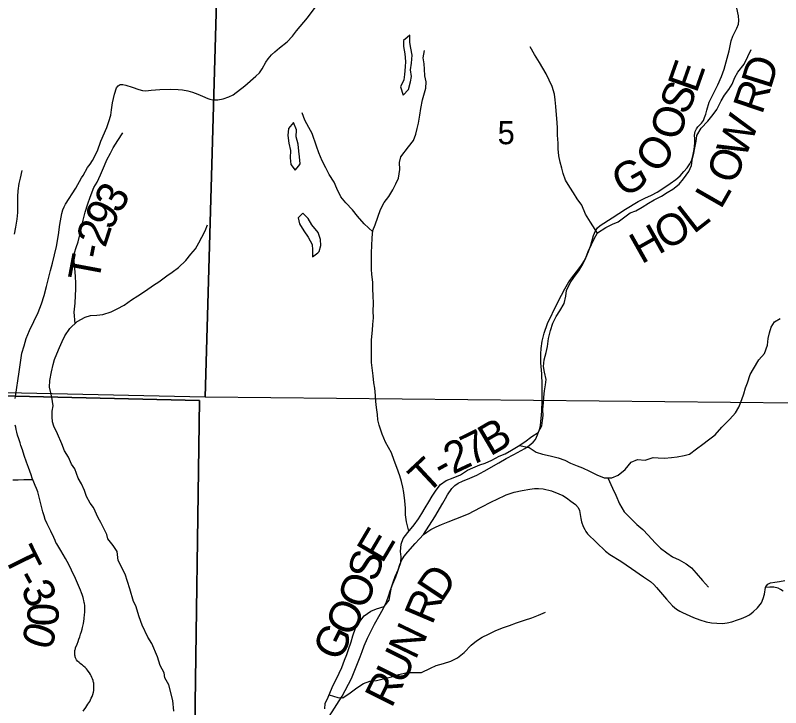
# Model space of a CAD drawing. Extents: x 0 to 34, y 0 to 22.
# Drawn here: x 5.34 to 6.729, y 17.07 to 18.326 of the extents above; entities that cross this region are included whole.
import ezdxf

# ---------------------------------------------------------------- set-up
doc = ezdxf.new("R2010")
doc.units = 0
for name, color, linetype in [('GM_X_County_Road', 7, 'Continuous'), ('GM_X_County_Road_Text', 7, 'Continuous'), ('GM_X_Minor_Lake', 7, 'Continuous'), ('GM_X_Minor_River', 7, 'Continuous'), ('GM_X_Rail_Line', 7, 'Continuous'), ('GM_X_Section', 7, 'Continuous'), ('GM_X_Section_Text', 7, 'Continuous'), ('GM_X_Township_Road', 7, 'Continuous'), ('GM_X_Township_Road_Text', 7, 'Continuous'), ('SH_Cut_Line', 7, 'Continuous')]:
    doc.layers.add(name, color=color, linetype=linetype)

msp = doc.modelspace()

# ---------------------------------------------------------------- linework, layer by layer
at = {"layer": 'GM_X_County_Road'}
for points in [[(6.081, 17.3843), (6.0871, 17.3887), (6.0943, 17.3932), (6.1037, 17.3984), (6.1137, 17.4027), (6.1257, 17.4074), (6.1397, 17.4129), (6.1623, 17.4221), (6.1845, 17.4331), (6.2053, 17.4442), (6.2131, 17.4481), (6.231, 17.4564), (6.2379, 17.4589), (6.2455, 17.461), (6.26, 17.4643), (6.2738, 17.4668), (6.2822, 17.4676), (6.2892, 17.4677), (6.2977, 17.467), (6.3129, 17.4634), (6.3261, 17.4583), (6.3335, 17.455), (6.3402, 17.451), (6.3484, 17.4448), (6.3565, 17.4387), (6.3614, 17.4336), (6.3641, 17.4282), (6.3661, 17.4136), (6.3677, 17.4073), (6.3706, 17.3991), (6.3734, 17.3936), (6.3756, 17.3901), (6.3785, 17.3858), (6.411, 17.3543), (6.4186, 17.3482), (6.439, 17.336), (6.4582, 17.323), (6.4802, 17.3076), (6.4927, 17.2993), (6.4984, 17.294), (6.5035, 17.2884), (6.5219, 17.267), (6.5325, 17.2553), (6.5397, 17.2491), (6.5458, 17.2452), (6.5504, 17.243), (6.5572, 17.2399), (6.5708, 17.2337), (6.5819, 17.2299), (6.5934, 17.2262), (6.6034, 17.2243), (6.6132, 17.2234), (6.623, 17.2233), (6.6316, 17.2241), (6.6405, 17.2263), (6.6505, 17.2299), (6.6577, 17.2321), (6.6665, 17.2356), (6.6724, 17.239), (6.679, 17.2441), (6.6868, 17.2516), (6.694, 17.2605), (6.6972, 17.2682), (6.6992, 17.2763), (6.7012, 17.2882), (6.7029, 17.2912), (6.7055, 17.2944), (6.7102, 17.297), (6.718, 17.2979), (6.7266, 17.2991), (6.7365, 17.3011)], [(5.9098, 17.0546), (5.9333, 17.0913), (5.9505, 17.1232), (5.9661, 17.1623), (5.9694, 17.1724), (5.9731, 17.1826), (5.9794, 17.1961), (5.9917, 17.2215), (6.0022, 17.2398), (6.0083, 17.2507), (6.014, 17.2625), (6.0173, 17.2725), (6.0202, 17.2822), (6.025, 17.2951), (6.0305, 17.3075), (6.0338, 17.3164), (6.0379, 17.3301), (6.0412, 17.3372), (6.0458, 17.345), (6.0527, 17.3529), (6.0657, 17.3679), (6.0733, 17.3767), (6.081, 17.3843)]]:
    msp.add_lwpolyline(points, dxfattribs=at)
at = {"layer": 'GM_X_Minor_Lake'}
for points in [[(6.044, 18.1813), (6.0534, 18.1916), (6.0575, 18.2053), (6.059, 18.2148), (6.0574, 18.2269), (6.0593, 18.2394), (6.06, 18.2535), (6.0576, 18.2663), (6.0561, 18.2766), (6.056, 18.2899), (6.0513, 18.286)], [(6.0513, 18.286), (6.0443, 18.2803), (6.0447, 18.2693), (6.047, 18.2564), (6.0479, 18.242), (6.0475, 18.2325), (6.0465, 18.2189), (6.045, 18.209), (6.0393, 18.1965), (6.044, 18.1813)], [(5.8452, 18.1319), (5.8361, 18.1208), (5.8347, 18.1079), (5.8366, 18.0939), (5.8393, 18.0807), (5.839, 18.0678), (5.8402, 18.0552), (5.8479, 18.045), (5.8544, 18.0529)], [(5.8544, 18.0529), (5.8573, 18.0565), (5.8561, 18.0693), (5.8545, 18.0796), (5.8533, 18.0925), (5.8499, 18.1057), (5.8502, 18.1183), (5.8452, 18.1319)], [(5.8619, 17.967), (5.8536, 17.959), (5.8559, 17.948), (5.8635, 17.9351), (5.8719, 17.9234), (5.8788, 17.9101), (5.8796, 17.9007), (5.8793, 17.8878), (5.8889, 17.8954)], [(5.8889, 17.8954), (5.8918, 17.8977), (5.8944, 17.9087), (5.894, 17.9197), (5.8897, 17.9322), (5.8783, 17.9458), (5.8718, 17.9575), (5.8619, 17.967)]]:
    msp.add_lwpolyline(points, dxfattribs=at)
at = {"layer": 'GM_X_Minor_River'}
for points in [[(6.0543, 17.3905), (6.05, 17.4073), (6.0484, 17.4198), (6.048, 17.4319), (6.0471, 17.4455), (6.0451, 17.4603), (6.0432, 17.4702), (6.0412, 17.4804), (6.0381, 17.4906), (6.0323, 17.5058), (6.0277, 17.5186), (6.0226, 17.5326), (6.0122, 17.5519), (6.0057, 17.5663), (6.0003, 17.5829), (5.9983, 17.5924), (5.9971, 17.6022), (5.9955, 17.6148), (5.9943, 17.6257), (5.9935, 17.6367), (5.9926, 17.65), (5.991, 17.6595), (5.9898, 17.672), (5.9882, 17.6818), (5.9866, 17.6966), (5.9863, 17.7376), (5.9881, 17.7547), (5.9892, 17.7653), (5.9899, 17.7771), (5.9898, 17.7899), (5.9901, 17.8025), (5.9896, 17.8184), (5.9892, 17.829), (5.9887, 17.8419), (5.9871, 17.8559), (5.9863, 17.8654), (5.9866, 17.8787), (5.9864, 17.8961), (5.9871, 17.9079), (5.9878, 17.9227), (5.9892, 17.9356), (5.9933, 17.9462), (5.9978, 17.9599), (6.003, 17.9736), (6.0094, 17.9866), (6.0177, 17.9972), (6.0252, 18.0098), (6.0308, 18.0205), (6.0353, 18.0307), (6.0382, 18.0463), (6.0374, 18.0592), (6.0396, 18.0694), (6.0539, 18.0877), (6.0626, 18.0992), (6.067, 18.1106), (6.0696, 18.1205), (6.0719, 18.1303), (6.074, 18.1451), (6.0758, 18.1573), (6.0792, 18.1725), (6.0851, 18.1938), (6.0854, 18.2051), (6.0834, 18.2161), (6.0826, 18.2283), (6.0822, 18.2381), (6.0802, 18.2487), (6.0824, 18.2624)], [(6.3962, 17.9312), (6.3836, 17.9511), (6.3748, 17.9654), (6.3682, 17.9817), (6.3598, 17.993), (6.3529, 18.004), (6.3464, 18.0142), (6.3387, 18.027), (6.3344, 18.0391), (6.3317, 18.049), (6.3286, 18.0599), (6.3266, 18.0713), (6.3254, 18.0838), (6.3253, 18.0944), (6.3241, 18.1085), (6.324, 18.1214), (6.3236, 18.1316), (6.322, 18.1456), (6.3211, 18.1604), (6.3199, 18.1729), (6.3183, 18.1828), (6.314, 18.1968), (6.309, 18.2085), (6.3033, 18.2198), (6.291, 18.2402), (6.2825, 18.255), (6.2741, 18.2686)], [(6.336, 17.8032), (6.3389, 17.8169), (6.3404, 17.8271), (6.3471, 17.8408), (6.3535, 17.8507), (6.3629, 17.8629), (6.3697, 17.8747), (6.3757, 17.888), (6.3798, 17.8976), (6.3858, 17.9101), (6.3907, 17.9208), (6.3963, 17.9314), (6.4118, 17.941), (6.4239, 17.9472), (6.4337, 17.9514), (6.4439, 17.9587), (6.456, 17.9678), (6.4659, 17.9717), (6.4776, 17.9782), (6.489, 17.9851), (6.4992, 17.9913), (6.5128, 17.9982), (6.5226, 18.0047), (6.5332, 18.0108), (6.5445, 18.0196), (6.5528, 18.0292), (6.5619, 18.0425), (6.5671, 18.0539), (6.5689, 18.0668), (6.5711, 18.0763), (6.573, 18.0858), (6.5752, 18.0976), (6.577, 18.1082), (6.5845, 18.1215), (6.5969, 18.1338), (6.6064, 18.146), (6.6131, 18.1555), (6.621, 18.1711), (6.627, 18.1814), (6.6345, 18.1913), (6.6409, 18.2012), (6.6458, 18.2133), (6.651, 18.2229), (6.6623, 18.2377), (6.6695, 18.2514), (6.6754, 18.264)], [(5.989, 17.9332), (5.9732, 17.948), (5.9613, 17.9616), (5.9521, 17.9733), (5.9399, 17.9861), (5.9311, 17.997), (5.9238, 18.0118), (5.9188, 18.0235), (5.91, 18.0375), (5.9034, 18.0492), (5.8969, 18.0624), (5.8911, 18.0764), (5.8865, 18.0889), (5.8787, 18.1116), (5.8726, 18.1226), (5.8653, 18.1358), (5.8606, 18.1491)], [(5.4487, 17.7668), (5.4469, 17.7879), (5.449, 17.8042), (5.4497, 17.8179), (5.45, 17.8293), (5.4499, 17.8403), (5.4495, 17.8524), (5.4482, 17.8676), (5.447, 17.8801), (5.4477, 17.8953), (5.451, 17.9048), (5.4544, 17.9154), (5.4566, 17.9253), (5.4592, 17.9348), (5.461, 17.9443), (5.4636, 17.9545), (5.4673, 17.969), (5.4718, 17.9842), (5.4762, 17.9963), (5.483, 18.0135), (5.4886, 18.0234), (5.4946, 18.0367), (5.5021, 18.0534), (5.5062, 18.0641), (5.5129, 18.0762), (5.5178, 18.0857), (5.5261, 18.0991), (5.5351, 18.1128)], [(5.3388, 17.9294), (5.3414, 17.9416), (5.344, 17.9564), (5.3447, 17.9686), (5.345, 17.9815), (5.3452, 17.9974), (5.3455, 18.0076), (5.3474, 18.0209), (5.3496, 18.0304), (5.3529, 18.0445)], [(5.4068, 17.6332), (5.4026, 17.6518), (5.4032, 17.6636), (5.4062, 17.6792), (5.4088, 17.6925), (5.4117, 17.702), (5.4158, 17.7122), (5.4203, 17.7233), (5.4252, 17.7347), (5.43, 17.7449), (5.4395, 17.7579), (5.4527, 17.7705), (5.467, 17.7786), (5.4769, 17.7813), (5.4883, 17.7825), (5.4989, 17.7837), (5.5141, 17.788), (5.5254, 17.7934), (5.5379, 17.8003), (5.5511, 17.8098), (5.5625, 17.8171), (5.5768, 17.8263), (5.5912, 17.8367), (5.601, 17.8428), (5.615, 17.8535), (5.6248, 17.8604), (5.6362, 17.8688), (5.6494, 17.8814), (5.6588, 17.8929), (5.6671, 17.9024), (5.6731, 17.9134), (5.6787, 17.9237), (5.6847, 17.9351), (5.6892, 17.9462)], [(5.9019, 17.068), (5.9026, 17.0782), (5.9078, 17.0896), (5.9123, 17.0999), (5.9172, 17.1113), (5.9224, 17.1212), (5.9281, 17.133), (5.9329, 17.1433), (5.9378, 17.1562), (5.9415, 17.1665), (5.9449, 17.176), (5.9497, 17.1897), (5.9527, 17.2007), (5.9575, 17.2144), (5.9654, 17.2265), (5.9733, 17.2372), (5.985, 17.2456), (5.9956, 17.2499), (6.0097, 17.2538), (6.0187, 17.2652), (6.0201, 17.2754), (6.0227, 17.2887), (6.0257, 17.2982), (6.0294, 17.3081), (6.0354, 17.3214), (6.0395, 17.3336), (6.0406, 17.3439), (6.039, 17.3533), (6.0404, 17.367), (6.0438, 17.3769), (6.0524, 17.3883), (6.0637, 17.402), (6.072, 17.4127), (6.078, 17.4226), (6.0837, 17.4329), (6.0908, 17.4436), (6.0964, 17.4538), (6.104, 17.4649), (6.1119, 17.4748), (6.1217, 17.4824), (6.1349, 17.4871), (6.1482, 17.4925), (6.1607, 17.5009), (6.1705, 17.5055), (6.183, 17.5105), (6.1925, 17.514), (6.205, 17.5194), (6.2182, 17.5263), (6.2288, 17.5309), (6.2402, 17.5371), (6.2523, 17.5444), (6.2647, 17.5524), (6.2776, 17.562), (6.2889, 17.5696), (6.2953, 17.5814), (6.2968, 17.5909), (6.2978, 17.6004), (6.2974, 17.6114), (6.2984, 17.6236), (6.2991, 17.6334), (6.3002, 17.6452), (6.302, 17.6558), (6.3031, 17.6657), (6.3004, 17.6789), (6.2984, 17.6888), (6.2998, 17.7013), (6.3035, 17.7146), (6.3058, 17.7253), (6.3076, 17.7401), (6.3113, 17.7541), (6.3153, 17.7674), (6.3213, 17.78), (6.3281, 17.7899), (6.336, 17.8032)], [(6.2547, 17.546), (6.2728, 17.5422), (6.2854, 17.534), (6.2968, 17.5302), (6.3105, 17.5269), (6.3249, 17.5236), (6.3375, 17.5195), (6.3478, 17.5139), (6.3596, 17.509), (6.3695, 17.5053), (6.382, 17.4993), (6.395, 17.4926), (6.4083, 17.4873), (6.4227, 17.4874), (6.4341, 17.4921), (6.4469, 17.5024), (6.4575, 17.5154), (6.4689, 17.5207), (6.4829, 17.5193), (6.4973, 17.5243), (6.5068, 17.5236), (6.5182, 17.523), (6.5307, 17.5238), (6.541, 17.5254), (6.5539, 17.5277), (6.5637, 17.5301), (6.5758, 17.5396), (6.5875, 17.5484), (6.5977, 17.5561), (6.6102, 17.5653), (6.6222, 17.579), (6.6366, 17.5935), (6.6468, 17.6053), (6.6528, 17.6156), (6.6584, 17.6293), (6.6621, 17.6396), (6.6651, 17.6502), (6.6684, 17.6597), (6.6736, 17.6745), (6.6793, 17.6848), (6.689, 17.7012), (6.6992, 17.7126), (6.7052, 17.7279), (6.7062, 17.74), (6.7088, 17.7503), (6.7118, 17.7605), (6.7178, 17.77), (6.728, 17.7762)], [(5.6278, 17.0642), (5.626, 17.0835), (5.6191, 17.1115), (5.6117, 17.1247), (5.6101, 17.1338), (5.603, 17.147), (5.5982, 17.1628), (5.588, 17.1866), (5.5806, 17.1982), (5.5704, 17.2201), (5.5649, 17.2352), (5.5592, 17.2549), (5.5546, 17.2632), (5.5481, 17.2858), (5.5394, 17.3127), (5.5272, 17.3375), (5.5251, 17.3534), (5.5177, 17.3647), (5.508, 17.3764), (5.5064, 17.3847), (5.4954, 17.4062), (5.4904, 17.4144), (5.4821, 17.4333), (5.4759, 17.4415), (5.4696, 17.4536), (5.4657, 17.4642), (5.4602, 17.4766), (5.4543, 17.4868), (5.4484, 17.5038), (5.4422, 17.512), (5.4367, 17.5249), (5.4296, 17.5361), (5.4245, 17.5486), (5.4166, 17.5671), (5.41, 17.5806), (5.408, 17.589), (5.4071, 17.5981), (5.4073, 17.6083), (5.409, 17.6178), (5.4068, 17.6332)], [(6.4152, 17.4874), (6.4236, 17.4685), (6.4298, 17.456), (6.4367, 17.4401), (6.4448, 17.4254), (6.4582, 17.4122), (6.4681, 17.4028), (6.4788, 17.3934), (6.4884, 17.3832), (6.501, 17.3692), (6.5109, 17.3598), (6.5224, 17.3512), (6.5327, 17.344), (6.5449, 17.3384), (6.5574, 17.3313), (6.567, 17.3241), (6.5754, 17.314), (6.5872, 17.3011), (6.5976, 17.2891)], [(5.9097, 17.0938), (5.9253, 17.089), (5.9348, 17.0883), (5.9477, 17.0975), (5.9598, 17.1063), (5.9718, 17.1143), (5.9832, 17.1182), (5.9954, 17.1194), (6.0079, 17.1225), (6.023, 17.126), (6.0359, 17.1307), (6.0511, 17.1342), (6.0628, 17.1339), (6.0773, 17.1343), (6.0935, 17.142), (6.1038, 17.1467), (6.117, 17.1502), (6.1307, 17.1544), (6.1428, 17.1606), (6.1545, 17.1705), (6.1673, 17.1839), (6.1771, 17.1915), (6.187, 17.198), (6.1987, 17.2038), (6.2108, 17.2099), (6.2241, 17.215), (6.2366, 17.2196), (6.2498, 17.2242), (6.2638, 17.2289), (6.2775, 17.2331), (6.2896, 17.2381), (6.3021, 17.2435)]]:
    msp.add_lwpolyline(points, dxfattribs=at)
at = {"layer": 'GM_X_Rail_Line'}
for points in [[(4.5408, 18.3763), (4.5402, 18.2851), (4.5419, 17.9684), (4.5429, 17.9404), (4.5474, 17.7028), (4.5489, 17.6578), (4.8158, 17.6467), (4.9624, 17.6496), (4.9797, 17.6498), (5.2052, 17.638), (5.3403, 17.635), (5.6743, 17.6274), (5.6656, 16.9939), (5.6628, 16.7899), (5.6628, 16.7878), (5.6614, 16.7344), (5.6594, 16.6485), (5.9824, 16.6436), (7.149, 16.6283)], [(7.149, 16.6283), (5.9824, 16.6436), (5.6594, 16.6485), (5.6614, 16.7344), (5.6628, 16.7878), (5.6628, 16.7899), (5.6656, 16.9939), (5.6743, 17.6274), (5.3403, 17.635), (5.2052, 17.638), (4.9797, 17.6498), (4.9624, 17.6496), (4.8158, 17.6467), (4.5489, 17.6578), (4.5478, 16.582), (4.5509, 15.5331), (4.5658, 14.9668), (4.5781, 14.1), (8.76, 14.1)]]:
    msp.add_lwpolyline(points, dxfattribs=at)
at = {"layer": 'GM_X_Section'}
for points in [[(5.7131, 18.626), (5.685, 17.6333), (4.5464, 17.6585), (4.5407, 18.3336), (4.5473, 18.6426)], [(5.7885, 18.6247), (6.7712, 18.6214), (6.7568, 17.6224), (5.685, 17.6333), (5.7131, 18.626)]]:
    msp.add_lwpolyline(points, close=True, dxfattribs=at)
at = {"layer": 'GM_X_Township_Road'}
for points in [[(5.3405, 17.6345), (5.3472, 17.6796), (5.3523, 17.713), (5.3562, 17.7266), (5.3601, 17.7399), (5.3661, 17.7545), (5.3742, 17.7707), (5.3816, 17.7869), (5.3877, 17.8029), (5.3924, 17.8179), (5.3968, 17.8341), (5.4043, 17.863), (5.4081, 17.8763), (5.4148, 17.9067), (5.4188, 17.9281), (5.4213, 17.9467), (5.4248, 17.9667), (5.4268, 17.9733), (5.4289, 17.9785), (5.4315, 17.9835), (5.4502, 18.0123), (5.4606, 18.0312), (5.4633, 18.0353), (5.4716, 18.05), (5.4761, 18.0562), (5.4803, 18.0628), (5.4892, 18.0803), (5.4957, 18.0975), (5.5062, 18.1223), (5.5103, 18.1332), (5.5134, 18.1451), (5.5151, 18.1547), (5.5165, 18.167), (5.5203, 18.1829), (5.5239, 18.1942), (5.5267, 18.198), (5.5306, 18.2003), (5.5354, 18.2007), (5.541, 18.1995), (5.5526, 18.1956), (5.5645, 18.1915), (5.5711, 18.1897), (5.5774, 18.1892), (5.5867, 18.19), (5.6024, 18.1917), (5.622, 18.1921), (5.6355, 18.1914), (5.6435, 18.1907), (5.6535, 18.189), (5.662, 18.1865), (5.6712, 18.1831), (5.68, 18.1791), (5.6894, 18.1753), (5.6935, 18.174), (5.6987, 18.173), (5.7075, 18.1729), (5.7176, 18.1747), (5.7275, 18.1779), (5.7357, 18.1819), (5.7565, 18.1981), (5.7766, 18.2158), (5.7831, 18.2219), (5.788, 18.229), (5.7946, 18.2412), (5.7991, 18.2471), (5.8051, 18.2541), (5.8112, 18.2598), (5.8198, 18.2668), (5.8337, 18.2781), (5.8429, 18.2883), (5.8506, 18.2981), (5.8704, 18.3213), (5.8895, 18.3476)], [(6.081, 17.3843), (6.1016, 17.4164), (6.1158, 17.441), (6.1207, 17.4498), (6.1242, 17.4562), (6.1323, 17.4677), (6.1379, 17.473), (6.144, 17.4773), (6.1518, 17.4812), (6.1648, 17.4866), (6.1774, 17.4921), (6.1909, 17.4994), (6.2173, 17.5142), (6.2311, 17.5223), (6.2446, 17.5294), (6.2645, 17.5406), (6.2725, 17.546), (6.2797, 17.5519), (6.284, 17.557), (6.2879, 17.5652), (6.291, 17.5749), (6.293, 17.582), (6.2957, 17.6078), (6.2964, 17.6271), (6.2959, 17.6561), (6.2954, 17.6759), (6.294, 17.696), (6.2937, 17.7118), (6.2942, 17.7218), (6.2962, 17.7351), (6.3, 17.7498), (6.3059, 17.7668), (6.3236, 17.8035), (6.3313, 17.8186), (6.3373, 17.8301), (6.3443, 17.8426), (6.3519, 17.8526), (6.3583, 17.861), (6.3663, 17.8708), (6.3739, 17.8834), (6.3803, 17.8975), (6.3843, 17.9094), (6.3891, 17.9266), (6.3927, 17.9352), (6.3967, 17.9407), (6.4015, 17.9448), (6.423, 17.9587), (6.4475, 17.9745), (6.4704, 17.9886), (6.4822, 17.9944), (6.4944, 18.0001), (6.5045, 18.0055), (6.5075, 18.0071), (6.5286, 18.021), (6.5388, 18.0281), (6.5465, 18.0351), (6.5532, 18.0426), (6.5591, 18.0496), (6.5638, 18.0565), (6.5674, 18.064), (6.5701, 18.0735), (6.5717, 18.0825), (6.573, 18.095), (6.5731, 18.1021), (6.5727, 18.1084), (6.5737, 18.1152), (6.5758, 18.1199), (6.5787, 18.124), (6.5853, 18.1307), (6.5886, 18.1353), (6.5909, 18.1404), (6.5932, 18.1466), (6.5949, 18.1542), (6.599, 18.1684), (6.6021, 18.1747), (6.6064, 18.1831), (6.6145, 18.2002), (6.6212, 18.2148), (6.6261, 18.2283), (6.6352, 18.2618), (6.6375, 18.2738), (6.6392, 18.2797), (6.6423, 18.2881), (6.6491, 18.3028), (6.6522, 18.3098), (6.6528, 18.3165), (6.652, 18.325), (6.6493, 18.3388)], [(5.3401, 17.6312), (5.3405, 17.6345)], [(5.3721, 17.4833), (5.3711, 17.4863), (5.3689, 17.4924), (5.3642, 17.5058), (5.3608, 17.5156), (5.3566, 17.5279), (5.3532, 17.5379), (5.3506, 17.5456), (5.3489, 17.5509), (5.346, 17.5599), (5.3452, 17.5626), (5.3445, 17.5647), (5.3431, 17.5701), (5.3419, 17.5749), (5.341, 17.579), (5.3403, 17.5828)], [(5.3721, 17.4833), (5.3685, 17.4833), (5.3638, 17.4833), (5.3558, 17.4833), (5.3453, 17.483), (5.336, 17.4828)], [(5.4632, 17.0639), (5.4684, 17.0709), (5.4722, 17.0765), (5.4754, 17.0818), (5.4782, 17.0874), (5.4797, 17.0908), (5.4809, 17.0943), (5.482, 17.0985), (5.4826, 17.1015), (5.4828, 17.1031), (5.4829, 17.1046), (5.483, 17.1065), (5.483, 17.1083), (5.4829, 17.1105), (5.4827, 17.1126), (5.4825, 17.1145), (5.4821, 17.1163), (5.4818, 17.118), (5.4813, 17.1199), (5.4804, 17.1228), (5.4794, 17.1252), (5.478, 17.1281), (5.4766, 17.1307), (5.4748, 17.1334), (5.4728, 17.1364), (5.471, 17.1385), (5.4692, 17.1406), (5.4669, 17.1429), (5.4639, 17.1456), (5.462, 17.1473), (5.4602, 17.1488), (5.4577, 17.1507), (5.4559, 17.1522), (5.4533, 17.1549), (5.4515, 17.1572), (5.4509, 17.1583), (5.4502, 17.1595), (5.4497, 17.1608), (5.4491, 17.1624), (5.4487, 17.1638), (5.4484, 17.1654), (5.4482, 17.1666), (5.4481, 17.1679), (5.4481, 17.1694), (5.4482, 17.171), (5.4484, 17.1726), (5.4486, 17.1742), (5.4489, 17.1757), (5.4493, 17.177), (5.4498, 17.1786), (5.4524, 17.1853), (5.4541, 17.1901), (5.4557, 17.1944), (5.4572, 17.1988), (5.4587, 17.2034), (5.4603, 17.2087), (5.4614, 17.2129), (5.4622, 17.2159), (5.4638, 17.2232), (5.4651, 17.2312), (5.4661, 17.2398), (5.4663, 17.2422), (5.4664, 17.2448), (5.4666, 17.2482), (5.4665, 17.2509), (5.4664, 17.2536), (5.4662, 17.2558), (5.4658, 17.259), (5.4654, 17.2613), (5.4646, 17.2646), (5.464, 17.2673), (5.4632, 17.2699), (5.4626, 17.2721), (5.4616, 17.2754), (5.4604, 17.2786), (5.4586, 17.2834), (5.4568, 17.2878), (5.4496, 17.3044), (5.4425, 17.3195), (5.4372, 17.3301), (5.4314, 17.3411), (5.4274, 17.3481), (5.4228, 17.3556), (5.4158, 17.3672), (5.4141, 17.3702), (5.4124, 17.3738), (5.41, 17.3787), (5.4045, 17.3904), (5.3983, 17.4038), (5.3948, 17.4117), (5.3924, 17.418), (5.3901, 17.4257), (5.3883, 17.433), (5.3865, 17.4402), (5.3848, 17.4474), (5.3829, 17.4546), (5.3809, 17.4616), (5.3787, 17.4679), (5.3766, 17.4733), (5.3738, 17.4796), (5.3721, 17.4833)], [(6.7332, 17.2817), (6.7284, 17.2849), (6.7244, 17.2869), (6.7164, 17.2888), (6.7089, 17.289), (6.7012, 17.2882)]]:
    msp.add_lwpolyline(points, dxfattribs=at)
at = {"layer": 'SH_Cut_Line'}
for points in [[(2.1, 14.1), (4.5781, 14.1), (4.5658, 14.9668), (4.5509, 15.5331), (4.5478, 16.582), (4.5489, 17.6578), (4.8158, 17.6467), (4.9624, 17.6496), (4.9797, 17.6498), (5.2052, 17.638), (5.3403, 17.635), (5.6743, 17.6274), (5.6656, 16.9939), (5.6628, 16.7899), (5.6628, 16.7878), (5.6614, 16.7344), (5.6594, 16.6485), (5.9824, 16.6436), (7.149, 16.6283)], [(7.149, 16.6283), (5.9824, 16.6436), (5.6594, 16.6485), (5.6614, 16.7344), (5.6628, 16.7878), (5.6628, 16.7899), (5.6656, 16.9939), (5.6743, 17.6274), (5.3403, 17.635), (5.2052, 17.638), (4.9797, 17.6498), (4.9624, 17.6496), (4.8158, 17.6467), (4.5489, 17.6578), (4.5478, 16.582), (4.5509, 15.5331), (4.5658, 14.9668), (4.5781, 14.1), (8.9, 14.1)]]:
    msp.add_lwpolyline(points, dxfattribs=at)

# ---------------------------------------------------------------- texts
at = {"layer": 'GM_X_County_Road_Text'}
for s, rotation, p in [('E', 59.4684, (6.0059, 17.3301)), ('S', 72.2109, (5.9955, 17.2966)), ('D', 56.3988, (6.1134, 17.2595)), ('O', 68.3265, (5.9756, 17.2462)), ('R', 67.01, (6.0965, 17.219)), ('O', 62.8762, (5.9504, 17.1963)), ('G', 63.6272, (5.9283, 17.1517)), ('N', 64.239, (6.0662, 17.1554)), ('U', 63.5733, (6.0437, 17.11)), ('R', 63.4402, (6.0228, 17.0681))]:
    msp.add_text(s, height=0.0568, rotation=rotation, dxfattribs=at).set_placement(p)
at = {"layer": 'GM_X_Section_Text'}
msp.add_text('5', height=0.0419, rotation=0, dxfattribs=at).set_placement((6.2153, 18.0922))
at = {"layer": 'GM_X_Township_Road_Text'}
for s, rotation, p in [('E', 70.5783, (6.5761, 18.1832)), ('D', 72.5794, (6.7104, 18.1901)), ('S', 65.4157, (6.5581, 18.1431)), ('R', 71.2541, (6.695, 18.1445)), ('O', 74.8335, (6.5458, 18.0972)), ('W', 68.5212, (6.6639, 18.064)), ('O', 53.8359, (6.5065, 18.0365)), ('O', 68.0961, (6.6451, 18.0172)), ('G', 29.0486, (6.4429, 17.9945)), ('3', 60.7973, (5.53, 17.9643)), ('L', 60.1092, (6.6201, 17.9726)), ('9', 61.2957, (5.5133, 17.9337)), ('L', 37.9571, (6.571, 17.9284)), ('O', 29.7471, (6.5202, 17.8987)), ('2', 71.9205, (5.5035, 17.903)), ('H', 29.373, (6.4762, 17.8739)), ('-', 78.3517, (5.4993, 17.8818)), ('T', 79.3624, (5.4915, 17.8402)), ('B', 30.3616, (6.2019, 17.5254)), ('7', 26.0142, (6.1665, 17.508)), ('2', 25.1598, (6.1343, 17.4928)), ('T', 42.9741, (6.0868, 17.4554)), ('-', 28.82, (6.1149, 17.4821)), ('T', 296.3351, (5.3183, 17.3458)), ('3', 295.2175, (5.3491, 17.2858)), ('-', 298.7039, (5.3383, 17.3055)), ('0', 269.0529, (5.3626, 17.2608)), ('0', 252.7285, (5.3627, 17.23))]:
    msp.add_text(s, height=0.0568, rotation=rotation, dxfattribs=at).set_placement(p)

doc.saveas('drawing.dxf')
